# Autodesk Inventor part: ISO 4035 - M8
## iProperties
Comments: To add or edit properties for Autodesk Inventor files, use iProperties.
Created: 2004-03
Part Number: ISO 4035 - M8
Vendor: Autodesk Inc.
Document SubType Name: Modeling
Designer: rak
Material: Default
Description: Hex Nut
Standard: ISO 4035
Size Designation: M8
Alert: To add or edit properties for Autodesk Inventor files, use iProperties.
Control State: 0
Master: False
Checked Out: False
Shininess: 64.0
Length Units: 11269
Angle Units: 11279
Time Units: 11290
Mass Units: 11283
Length Display Precision: 3
Angle Display Precision: 2
Compacted: True
EGR: 1
Density: 0.0
Volumn: 0.0
Area: 0.0
PropertySet Name: Model Information
Author: rak
Revision Number: 8
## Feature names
1. Body [Extrusion]
2. Chamfer1 [Revolution]
3. Thread [Hole]
4. Chamfer2
5. Chamfer3
